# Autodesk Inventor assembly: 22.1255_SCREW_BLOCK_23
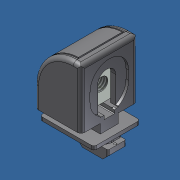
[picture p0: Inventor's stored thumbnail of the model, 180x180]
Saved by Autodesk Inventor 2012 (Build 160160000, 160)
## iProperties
Created: 2016-06
Part Number: 22.1255_SCREW_BLOCK_23
Document SubType Name: Assembly
Designer: Admin
Author: Admin
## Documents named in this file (4)
- C:\Andys Backup Data\ANDY'S INVENTOR\INVENTOR LIBRARIES\PARTS LIBRARY\30 SERIES\22.1255_SCREW_BLOCK_23.iam
- C:\Andys Backup Data\ANDY'S INVENTOR\INVENTOR LIBRARIES\PARTS LIBRARY\30 SERIES\SUBCOMPONENTS\22.1255_SCREW_BLOCK_23_BODY.ipt
- C:\Andys Backup Data\ANDY'S INVENTOR\INVENTOR LIBRARIES\PARTS LIBRARY\30 SERIES\SUBCOMPONENTS\SCREW BLOCK M6 NUT.ipt
- C:\Andys Backup Data\ANDY'S INVENTOR\INVENTOR LIBRARIES\PARTS LIBRARY\30 SERIES\SUBCOMPONENTS\SCREW BLOCK COVER.ipt
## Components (3 placed, 3 different names)
1. 22.1255_SCREW_BLOCK_23_BODY:1 — Mate:1, Mate:2, Mate:3, Mate:4, Mate:5, Mate:6
2. SCREW BLOCK M6 NUT:1 — Mate:1, Mate:2, Mate:3
3. SCREW BLOCK COVER:1 — Mate:4, Mate:5, Mate:6
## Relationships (6: Mate 6)
- Mate:1: 22.1255_SCREW_BLOCK_23_BODY:1 ↔ SCREW BLOCK M6 NUT:1
- Mate:2: 22.1255_SCREW_BLOCK_23_BODY:1 ↔ SCREW BLOCK M6 NUT:1
- Mate:3: 22.1255_SCREW_BLOCK_23_BODY:1 ↔ SCREW BLOCK M6 NUT:1
- Mate:4: 22.1255_SCREW_BLOCK_23_BODY:1 ↔ SCREW BLOCK COVER:1
- Mate:5: 22.1255_SCREW_BLOCK_23_BODY:1 ↔ SCREW BLOCK COVER:1
- Mate:6: 22.1255_SCREW_BLOCK_23_BODY:1 ↔ SCREW BLOCK COVER:1
